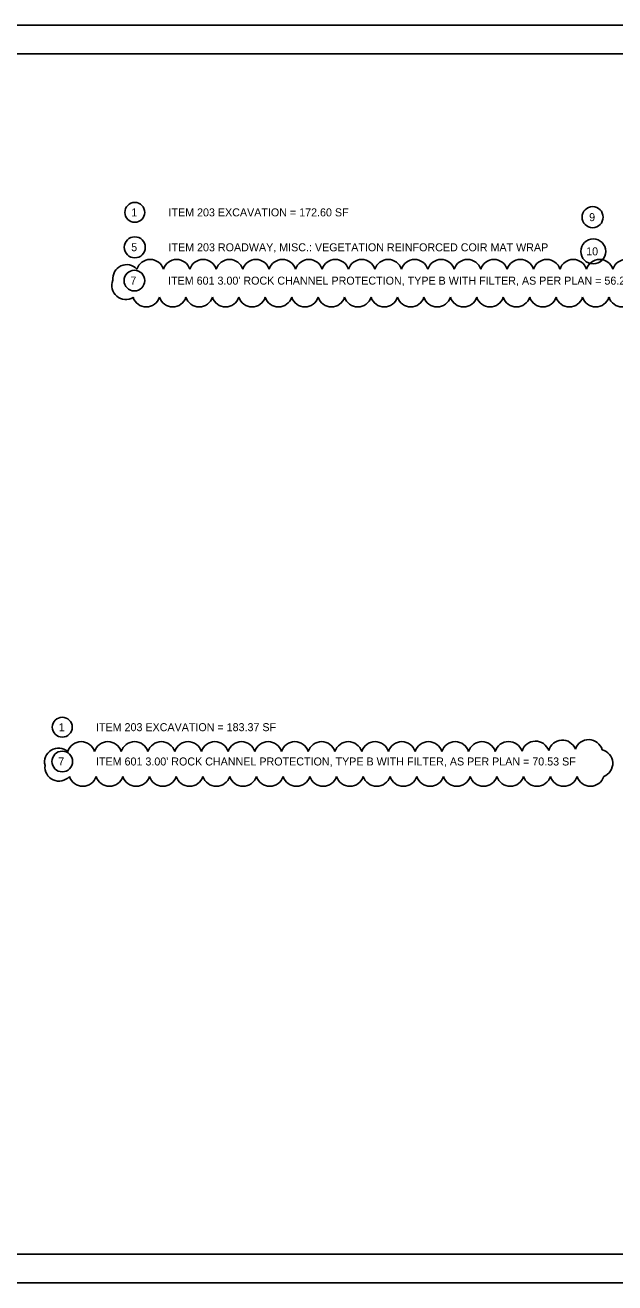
# Model space of a CAD drawing. Extents: x -34.1 to 34, y 0 to 22.
# Drawn here: x 11.9 to 22.2, y 0 to 22 of the extents above; entities that cross this region are included whole.
import ezdxf

# ---------------------------------------------------------------- set-up
doc = ezdxf.new("R2010")
doc.units = 0
for name, color, linetype in [('CS-ANNO', 7, 'Continuous'), ('CS-ANNO-MATC', 7, 'Continuous'), ('CS-ANNO-MATC-TEXT', 7, 'Continuous')]:
    doc.layers.add(name, color=color, linetype=linetype)

msp = doc.modelspace()

# ---------------------------------------------------------------- linework, layer by layer
at = {"layer": 'CS-ANNO'}
msp.add_lwpolyline([(0, 0), (34, 0), (34, 22), (0, 22)], close=True, dxfattribs=at)
at = {"layer": 'CS-ANNO-MATC'}
msp.add_lwpolyline([(1.5, 21.5), (33.5, 21.5), (33.5, 0.5), (1.5, 0.5)], close=True, dxfattribs=at)
at = {"layer": 'CS-ANNO-MATC-TEXT'}
for centre, radius in [((13.813, 18.725), 0.174), ((21.814, 18.641), 0.184), ((13.813, 18.114), 0.184), ((21.825, 18.042), 0.218), ((13.806, 17.531), 0.181), ((12.546, 9.72), 0.174), ((12.546, 9.12), 0.181)]:
    msp.add_circle(centre, radius, dxfattribs=at)
for centre, radius, start, end in [((14.082, 17.659), 0.242, 17.5, 162.5), ((14.544, 17.659), 0.242, 17.5, 162.5), ((15.006, 17.659), 0.242, 17.5, 162.5), ((15.468, 17.659), 0.242, 17.5, 162.5), ((15.93, 17.659), 0.242, 17.5, 162.5), ((16.392, 17.659), 0.242, 17.5, 162.5), ((16.855, 17.659), 0.242, 17.5, 162.5), ((17.317, 17.659), 0.242, 17.5, 162.5), ((17.779, 17.659), 0.242, 17.5, 162.5), ((18.241, 17.659), 0.242, 17.5, 162.5), ((18.703, 17.659), 0.242, 17.5, 162.5), ((19.165, 17.659), 0.242, 17.5, 162.5), ((19.627, 17.659), 0.242, 17.5, 162.5), ((20.089, 17.659), 0.242, 17.5, 162.5), ((20.551, 17.659), 0.242, 17.5, 162.5), ((21.013, 17.659), 0.242, 17.5, 162.5), ((21.475, 17.659), 0.242, 17.5, 162.5), ((21.937, 17.659), 0.242, 17.5, 162.5), ((22.399, 17.659), 0.242, 17.5, 162.5), ((13.672, 17.569), 0.242, 42.3398, 187.3398), ((13.655, 17.444), 0.242, 157.0653, 302.0653), ((14.014, 17.312), 0.242, 197.5, 342.5), ((14.476, 17.312), 0.242, 197.5, 342.5), ((14.938, 17.312), 0.242, 197.5, 342.5), ((15.4, 17.312), 0.242, 197.5, 342.5), ((15.862, 17.312), 0.242, 197.5, 342.5), ((16.324, 17.312), 0.242, 197.5, 342.5), ((16.787, 17.312), 0.242, 197.5, 342.5), ((17.249, 17.312), 0.242, 197.5, 342.5), ((17.711, 17.312), 0.242, 197.5, 342.5), ((18.173, 17.312), 0.242, 197.5, 342.5), ((18.635, 17.312), 0.242, 197.5, 342.5), ((19.097, 17.312), 0.242, 197.5, 342.5), ((19.559, 17.312), 0.242, 197.5, 342.5), ((20.021, 17.312), 0.242, 197.5, 342.5), ((20.483, 17.312), 0.242, 197.5, 342.5), ((20.945, 17.312), 0.242, 197.5, 342.5), ((21.407, 17.312), 0.242, 197.5, 342.5), ((21.869, 17.312), 0.242, 197.5, 342.5), ((22.331, 17.312), 0.242, 197.5, 342.5), ((12.876, 9.222), 0.245, 17.5, 162.5), ((13.343, 9.222), 0.245, 17.5, 162.5), ((13.81, 9.222), 0.245, 17.5, 162.5), ((14.277, 9.222), 0.245, 17.5, 162.5), ((14.744, 9.222), 0.245, 17.5, 162.5), ((15.211, 9.222), 0.245, 17.5, 162.5), ((15.677, 9.222), 0.245, 17.5, 162.5), ((16.144, 9.222), 0.245, 17.5, 162.5), ((16.611, 9.222), 0.245, 17.5, 162.5), ((17.078, 9.222), 0.245, 17.5, 162.5), ((17.545, 9.222), 0.245, 17.5, 162.5), ((18.012, 9.222), 0.245, 17.5, 162.5), ((18.479, 9.222), 0.245, 17.5, 162.5), ((18.946, 9.222), 0.245, 17.5, 162.5), ((19.413, 9.222), 0.245, 17.5, 162.5), ((19.88, 9.222), 0.245, 17.5416, 162.5416), ((20.347, 9.224), 0.245, 17.9339, 162.9339), ((20.815, 9.231), 0.245, 18.7034, 163.7034), ((21.284, 9.249), 0.245, 20.777, 165.777), ((21.745, 9.257), 0.245, 16.14, 161.14), ((12.482, 9.11), 0.245, 49.1676, 194.1676), ((21.921, 9.087), 0.245, 291.0344, 76.0344), ((12.488, 9.021), 0.245, 173.0803, 318.0803), ((12.904, 8.931), 0.245, 197.5, 342.5), ((13.371, 8.931), 0.245, 197.5, 342.5), ((13.837, 8.931), 0.245, 197.5, 342.5), ((14.304, 8.931), 0.245, 197.5, 342.5), ((14.771, 8.931), 0.245, 197.5, 342.5), ((15.238, 8.931), 0.245, 197.5, 342.5), ((15.705, 8.931), 0.245, 197.5, 342.5), ((16.172, 8.931), 0.245, 197.5, 342.5), ((16.639, 8.931), 0.245, 197.5, 342.5), ((17.106, 8.931), 0.245, 197.5, 342.5), ((17.573, 8.931), 0.245, 197.5, 342.5), ((18.04, 8.931), 0.245, 197.5, 342.5), ((18.507, 8.931), 0.245, 197.5, 342.5), ((18.974, 8.931), 0.245, 197.5, 342.5), ((19.441, 8.931), 0.245, 197.5, 342.5), ((19.908, 8.931), 0.245, 197.5, 342.5), ((20.375, 8.931), 0.245, 197.5, 342.5), ((20.842, 8.931), 0.245, 197.5, 342.5), ((21.309, 8.931), 0.245, 197.5, 342.5), ((21.775, 8.932), 0.245, 197.7222, 342.7222)]:
    msp.add_arc(centre, radius, start, end, dxfattribs=at)

# ---------------------------------------------------------------- texts
for s, p in [('1', (13.752, 18.655)), ('ITEM 203 EXCAVATION = 172.60 SF', (14.402, 18.655)), ('9', (21.753, 18.572)), ('5', (13.75, 18.046)), ('ITEM 203 ROADWAY, MISC.: VEGETATION REINFORCED COIR MAT WRAP', (14.402, 18.044)), ('10', (21.701, 17.973)), ('7', (13.736, 17.462)), ("ITEM 601 3.00' ROCK CHANNEL PROTECTION, TYPE B WITH FILTER, AS PER PLAN = 56.21 SF", (14.395, 17.461)), ('1', (12.485, 9.65)), ('ITEM 203 EXCAVATION = 183.37 SF', (13.135, 9.65)), ('7', (12.476, 9.051)), ("ITEM 601 3.00' ROCK CHANNEL PROTECTION, TYPE B WITH FILTER, AS PER PLAN = 70.53 SF", (13.135, 9.05))]:
    msp.add_text(s, height=0.14, dxfattribs=at).set_placement(p)

doc.saveas('drawing.dxf')
